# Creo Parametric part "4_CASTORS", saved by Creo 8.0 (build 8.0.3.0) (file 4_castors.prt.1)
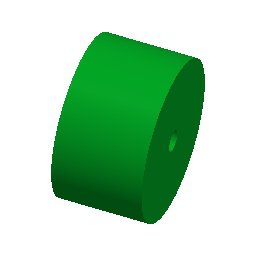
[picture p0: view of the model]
Units: millimeter Newton Second (mmNs); MM, TONNE, SECS

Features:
  1. datum plane "DTM1"
  2. protrusion
  3. datum plane "DTM2"
  4. cut

Layers: 0_ALL_AXIS, 0_ALL_CSYS, 0_ALL_CURVES, 0_ALL_PLANES, 0_ALL_POINTS, 0_ALL_SURFS, CASTORS

Surfaces: 2 plane, 2 cylinder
